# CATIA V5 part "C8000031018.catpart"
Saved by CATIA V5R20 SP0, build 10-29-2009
Part number: C8000031018
Source: Unknown
Property "A": "30"
Property "ARTICLENO": "C8000031018"
Property "B": "13"
Property "BOMINFO": "C8000031018"
Property "C": "46"
Property "CA": "C8000031018"
Property "D1": "38"
Property "DES": "ROTATING EYEBOLT WITH RING Ton 0,3 M10x18"
Property "E": "50"
Property "H": "105"
Property "L": "18"
Property "LINA": "C8000031018"
Property "NB": "C8000031018"
Property "NBSYN": "$CODE."
Property "NN": "C800"
Property "NT": "Rotating eyebolt with ring"
Property "SIZE": "M10"
Property "SUPPLIER": "CF"
Property "SW": "30"
Property "WEIGHT": "480"
Property "WLL": "0.30"
Bounding box of the stored display mesh (mm): x -27.837 to 28, y -18 to 117.837, z -19 to 19
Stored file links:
  C:\Users\Utente\Desktop\3D files 800\C8000031018.catpart
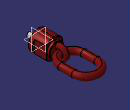
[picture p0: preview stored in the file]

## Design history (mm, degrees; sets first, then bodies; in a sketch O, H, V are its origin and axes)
Body1 "Geometry.1" (main body)
  Solid1 "C8000031018.catpart": solid without history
